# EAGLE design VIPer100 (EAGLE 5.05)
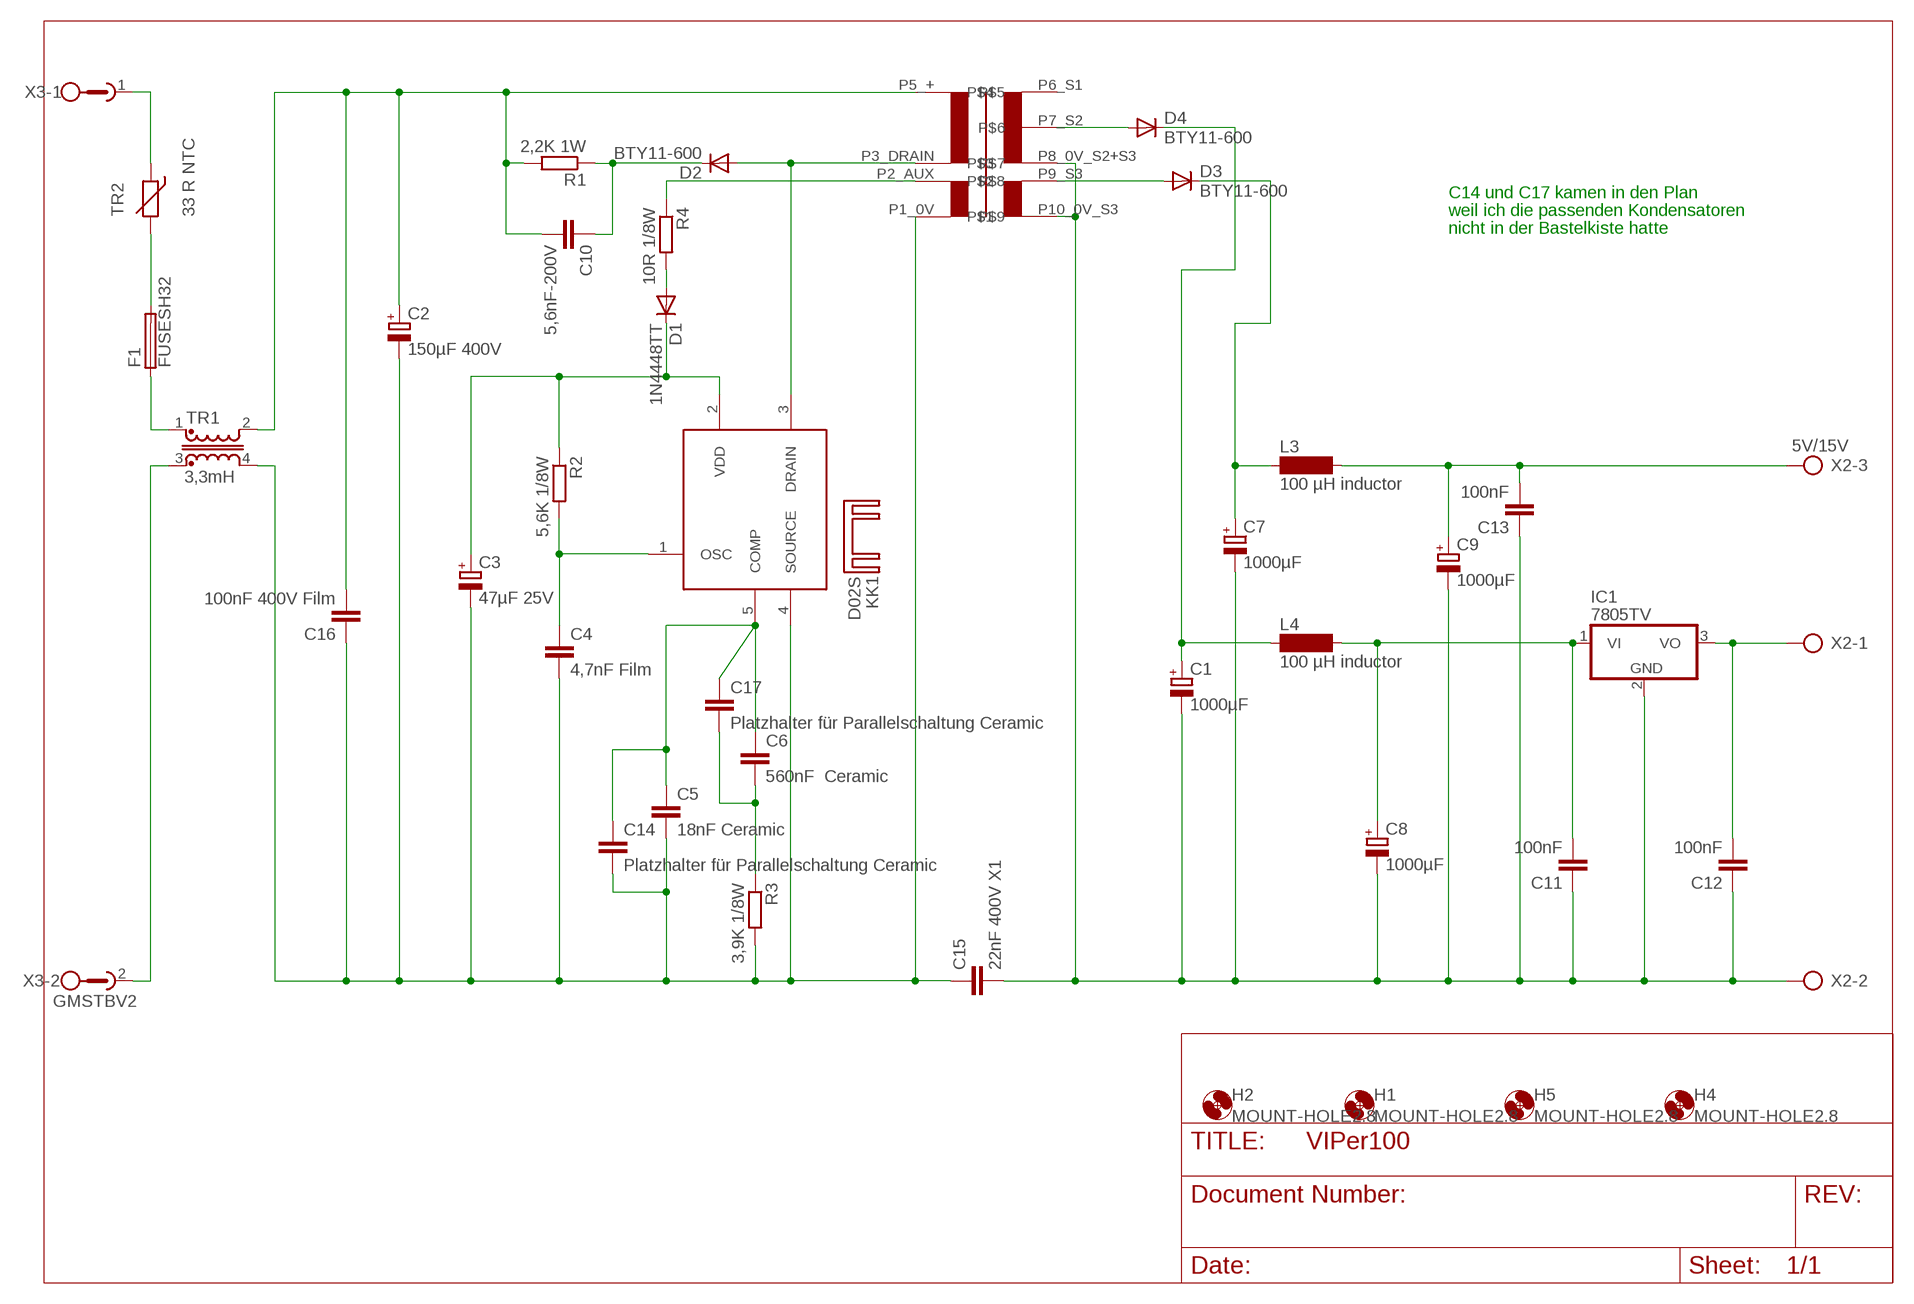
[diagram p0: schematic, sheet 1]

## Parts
C1  1000µF  CPOL-EUE5-8.5  [E5-8,5]
C2  150µF 400V  CPOL-EUE10-22.5  [EB22,5D]
C3  47µF 25V  CPOL-EUE5-5  [E5-5]
C4  4,7nF Film  C-EU050-025X075  [C050-025X075]
C5  18nF Ceramic  C-EU050-024X044  [C050-024X044]
C6  560nF Ceramic  C-EU050-024X044  [C050-024X044]
C7  1000µF  CPOL-EUE5-13  [E5-13]
C8  1000µF  CPOL-EUE5-8.5  [E5-8,5]
C9  1000µF  CPOL-EUE5-8.5  [E5-8,5]
C10  5,6nF-200V  C-EU225-074X268  [C225-074X268]
C11  100nF  C-EU025-025X050  [C025-025X050]
C12  100nF  C-EU025-025X050  [C025-025X050]
C13  100nF  C-EU025-025X050  [C025-025X050]
C14  Platzhalter für Parallelschaltung Ceramic  C-EU050-024X044  [C050-024X044]
C15  22nF 400V X1  C-EU102-064X133  [C102-064X133]
C16  100nF 400V Film  C-EU075-042X103  [C075-042X103]
C17  Platzhalter für Parallelschaltung Ceramic  C-EU050-024X044  [C050-024X044]
D1  1N4448TT  1N4148TT  [DO35-10]
D2  BTY11-600  1N4004GR  [C2992]
D3  BTY11-600  1N4004GR  [C2992]
D4  BTY11-600  1N4004GR  [C2992]
F1  FUSESH32  [SH32]
H1  MOUNT-HOLE2.8  [2,8]
H2  MOUNT-HOLE2.8  [2,8]
H4  MOUNT-HOLE2.8  [2,8]
H5  MOUNT-HOLE2.8  [2,8]
IC1  7805TV  [TO220V]
KK1  D02S  [D02S]
L3  100 µH inductor  SD12-1000  [SD12_1000]
L4  100 µH inductor  SD12-1000  [SD12_1000]
R1  2,2K 1W  R-EU0613/15  [P0613/15]
R2  5,6K 1/8W  R-EU0204/7L  [0207/7L]
R3  3,9K 1/8W  R-EU0207/7Q  [0207/7Q]
R4  10R 1/8W  R-EU0204/7L  [0207/7L]
TR1  3,3mH  U15-TRANSFORMER  [U15]
TR2  33 R NTC  THERMISTOR_R-7,5  [R-7,5]
U$2  MYRRA - 74030 - TRANSFORMATOR, EE25, 30W  HF_TRAFO_MYRRA  [EE25]
VIPER100A  VIPER100TO220HV  VIPER1002HINTEN  [T05D]
X2  5V/15V  AK300/3  [AK300/3]
X3  GMSTBV2  [GMSTBV2]

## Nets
GND1: C2.- C3.- C4.2 C5.2 C14.2 C15.1 C16.1 R3.P$2 TR1.4 U$2.P1_0V VIPER100A.4(SOURCE)
GND2: C1.- C7.- C8.- C9.- C11.1 C12.1 C13.1 C15.2 IC1.2(GND) U$2.P8_0V_S2+S3 U$2.P10_0V_S3 X2.2
N$1: C2.+ C10.2 C16.2 R1.2 TR1.2 U$2.P5_+
N$2: D2.A U$2.P3_DRAIN VIPER100A.3(DRAIN)
N$3: TR2.1 X3.1
N$4: F1.2A TR2.2
N$5: R4.P$1 U$2.P2_AUX
N$6: D1.A R4.P$2
N$7: C3.+ D1.C R2.P$1 VIPER100A.2(VDD)
N$8: C10.1 D2.C R1.1
N$9: C5.1 C6.1 C14.1 C17.1 VIPER100A.5(COMP)
N$10: C6.2 C17.2 R3.P$1
N$11: C4.1 R2.P$2 VIPER100A.1(OSC)
N$12: TR1.3 X3.2
N$13: F1.1A TR1.1
N$14: D4.A U$2.P7_S2
N$15: C8.+ C11.2 IC1.1(VI) L4.2
N$16: D3.A U$2.P9_S3
N$18: C1.+ D4.C L4.1
N$19: C7.+ D3.C L3.1
N$20: C9.+ C13.2 L3.2 X2.3
N$22: C12.2 IC1.3(VO) X2.1
Unconnected: U$2.P6_S1

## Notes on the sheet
- C14 und C17 kamen in den Plan
- weil ich die passenden Kondensatoren
- nicht in der Bastelkiste hatte

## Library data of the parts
C1-C3 C7-C9 = rcl:CPOL-EU: POLARIZED CAPACITOR, European symbol
C4-C6 C10-C17 = rcl:C-EU: CAPACITOR, European symbol
D1 = Axel2:1N4148: DIODE
D2-D4 = Axel2:1N4004: DIODE
F1 = fuse:FUSE: Fuse
H1 H2 H4 H5 = holes:MOUNT-HOLE: MOUNTING HOLE with drill center marker
IC1 = linear:78*: Positive VOLTAGE REGULATOR Source: http://cache.national.com/ds/LM/LM78L05.pdf http://www.fairchildsemi.com/ds/LM/LM7805.pdf
KK1 = heatsink:D02S: HEATSINK
L3 L4 = inductor-neosid:SD12: INDUCTOR
R1-R4 = Axel2:R-EU: RESISTOR, European symbol
TR1 = inductor-neosid:U15: TRANSFORMER U15
TR2 = discrete:THERMISTOR_: Thermo Resistor
U$2 = Axel2:HF_TRAFO_MYRRA
VIPER100A = Axel2:VIPER100
X2 = Axel2:AK300/3: CONNECTOR
X3 = con-phoenix-508:GMSTBV2: PHOENIX

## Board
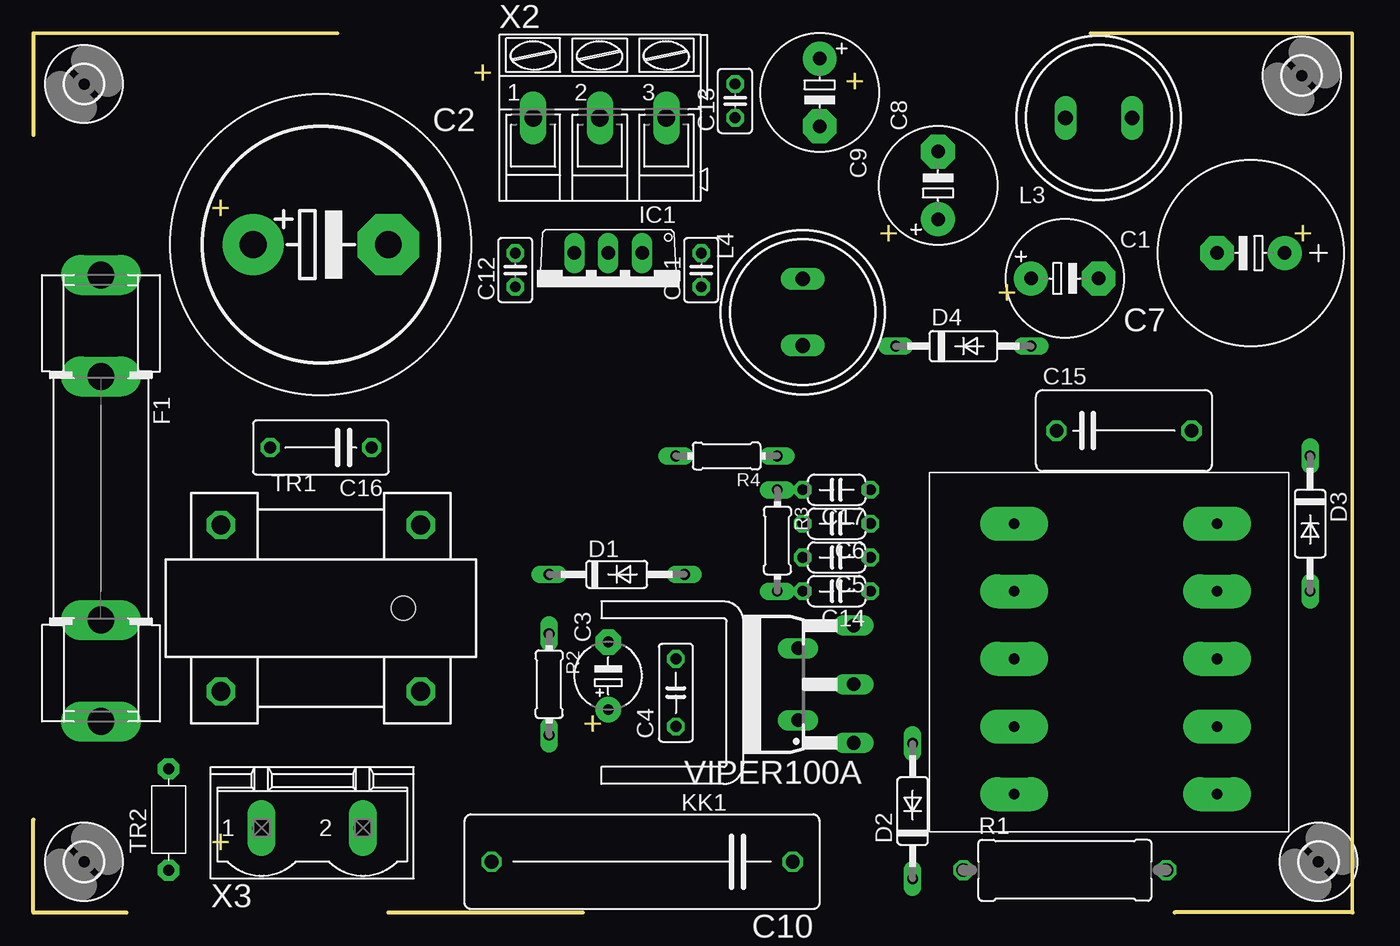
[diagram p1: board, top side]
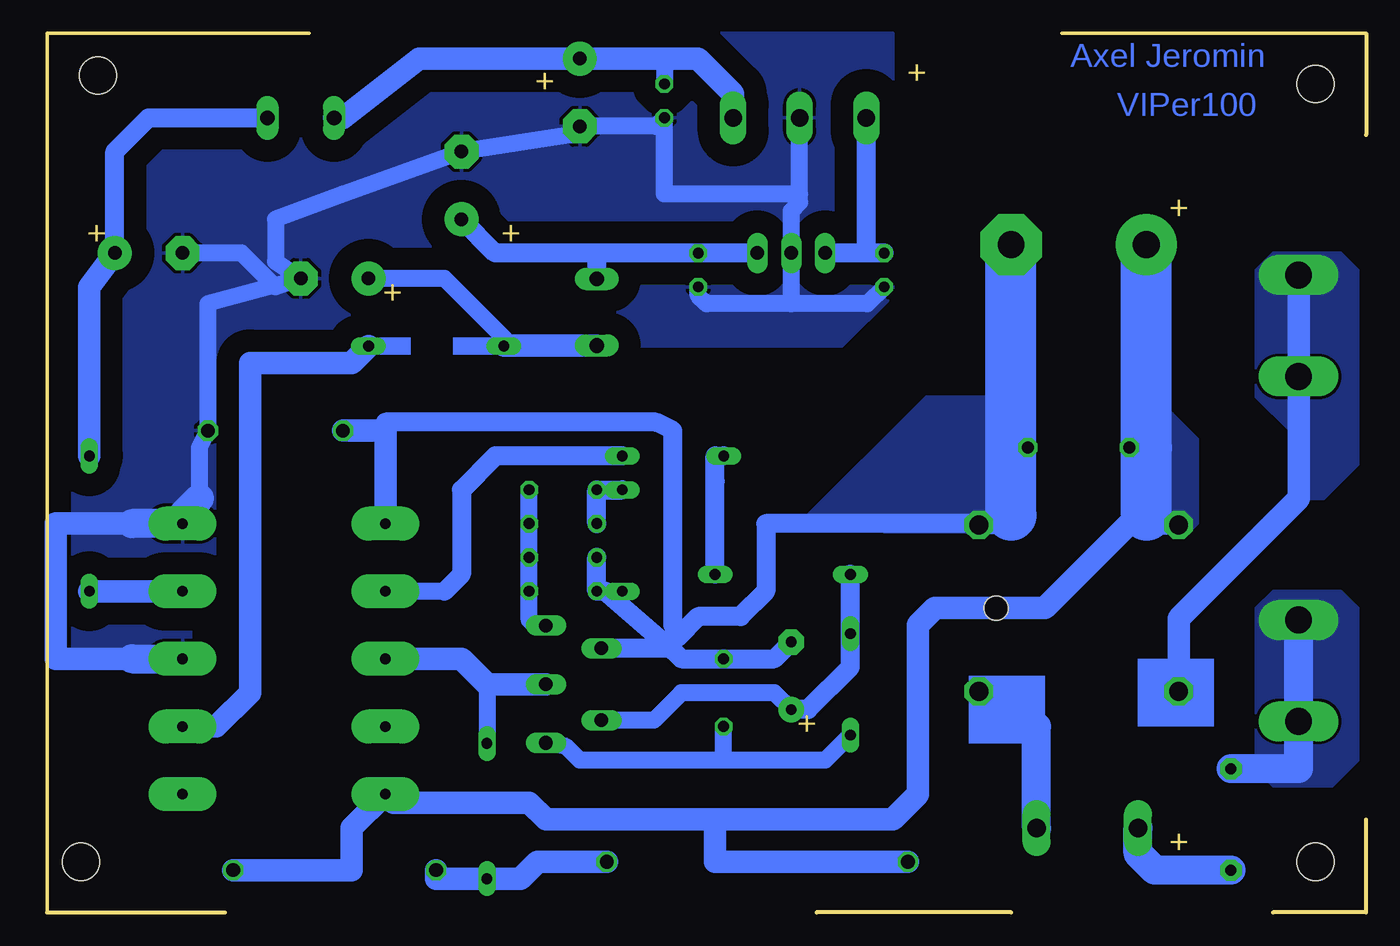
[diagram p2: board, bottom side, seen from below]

Size 99.06 x 66.04 mm. Coordinates in mm from the lower left corner, seen from the top.
Outline: 0,58.42 0,66.04 22.86,66.04
Outline: 0,6.99 0,0 6.99,0
Outline: 85.72,0 99.06,0 99.06,66.04 79.38,66.04
Outline: 26.67,0 41.27,0
Copper layers (1*16): Top 0.035mm / dielectric 1.5mm / Bottom 0.035mm
Design rules "default *": minimum track width 10mil, minimum drill 24mil, track to track 8mil, track to pad 8mil, pad to pad 8mil, via to via 8mil, smd to smd 8mil, copper to edge 40mil, drill to drill 8mil, minimum pad ring 10mil, minimum via ring 8mil, stop-mask expansion 4mil, vias tented up to drill 0mil, thermal gap 10mil

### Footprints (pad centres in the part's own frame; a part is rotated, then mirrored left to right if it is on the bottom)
E5-8,5 = drill 1.016 pad 2.54 round: + -2.54,0 | drill 1.016 pad 2.54 octagon: - 2.54,0
EB22,5D = drill 2.007 pad 4.597 round: + -5.08,0 | drill 2.007 pad 4.597 octagon: - 5.08,0
E5-5 = drill 0.813 pad 1.905 round: + -2.54,0 | drill 0.813 pad 1.905 octagon: - 2.54,0
C050-025X075 = drill 0.813 octagon: 1 -2.54,0; 2 2.54,0
C050-024X044 = drill 0.813 octagon: 1 -2.54,0; 2 2.54,0
E5-13 = drill 1.016 pad 2.54 round: + -2.54,0 | drill 1.016 pad 2.54 octagon: - 2.54,0
C225-074X268 = drill 1.016 octagon: 1 -11.303,0; 2 11.303,0
C025-025X050 = drill 0.813 octagon: 1 -1.27,0; 2 1.27,0
C102-064X133 = drill 1.016 octagon: 1 -5.08,0; 2 5.08,0
C075-042X103 = drill 0.914 octagon: 1 -3.81,0; 2 3.81,0
DO35-10 = drill 0.813 long: A 5.08,0; C -5.08,0
C2992 = drill 0.813 long: A 5.08,0; C -5.08,0
SH32 = drill 2.007 long: 1A -16.764,0; 1B -9.144,0; 2A 9.144,0; 2B 16.764,0
2,8 = hole 2.8: 0,0
TO220V = drill 1.016 long: 1 -2.54,-2.54; 2 0,-2.54; 3 2.54,-2.54
SD12_1000 = drill 1.1 long: 1 -2.5,0; 2 2.5,0
P0613/15 = drill 1.016 octagon: 1 -7.62,0; 2 7.62,0
0207/7L = drill 0.8 long: P$1 -3.81,0; P$2 3.81,0
0207/7Q = drill 0.8 long: P$1 -3.81,0; P$2 3.81,0
U15 = drill 1.422 octagon: 1 -7.5,-6.25; 2 -7.5,6.25; 3 7.5,-6.25; 4 7.5,6.25 | hole 1.8: 6.2,0
R-7,5 = drill 0.813 pad 1.6 octagon: 1 -3.81,0; 2 3.81,0
EE25 = drill 0.8 pad 2.54 long: P1_0V -7.62,10.16; P2_AUX -7.62,5.08; P3_DRAIN -7.62,0; P4_FREI -7.62,-5.08; P5_+ -7.62,-10.16; P6_S1 7.62,-10.16; P7_S2 7.62,-5.08; P8_0V_S2+S3 7.62,0; P9_S3 7.62,5.08; P10_0V_S3 7.62,10.16
T05D = drill 1.016 long: 1 -4.404,-5.08; 2 -2.702,-0.914; 3 0,-5.08; 4 2.702,-0.914; 5 4.404,-5.08
AK300/3 = drill 1.321 long: 1 -5.004,0; 2 0,0; 3 5.004,0
GMSTBV2 = drill 1.397 long: 1 -3.81,0; 2 3.81,0

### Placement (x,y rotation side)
C1  77.47,47.62 0 top
C2  21.59,50.16 0 top
C3  43.18,17.78 90 top
C4  48.26,16.51 90 top
C5  60.33,26.67 180 top
C6  60.33,29.21 180 top
C7  91.44,49.53 180 top
C8  67.94,54.61 90 top
C9  59.05,61.59 270 top
C10  45.72,3.81 180 top
C11  50.16,48.26 90 top
C12  36.2,48.26 90 top
C13  52.7,60.96 90 top
C14  60.33,24.13 180 top
C15  81.92,36.2 0 top
C16  21.59,34.92 180 top
C17  60.33,31.75 180 top
D1  43.81,25.4 0 top
D2  66.04,7.62 90 top
D3  95.89,29.21 270 top
D4  69.85,42.55 0 top
F1  5.08,31.11 270 top
H1  3.81,62.23 0 top
H2  95.25,62.87 0 top
H4  3.81,3.81 0 top
H5  96.52,3.81 0 top
IC1  43.18,46.99 180 top
KK1  52.07,16.51 90 top
L3  80.01,59.69 180 top
L4  57.78,45.09 90 top
R1  77.47,3.17 0 top
R2  38.73,17.14 270 top
R3  55.88,27.94 270 top
R4  52.07,34.29 180 top
TR1  21.59,22.86 0 top
TR2  10.16,6.99 90 top
U$2  81.28,19.05 0 top
VIPER100A  56.52,17.14 90 top
X2  42.55,59.69 0 top
X3  20.95,6.35 0 top

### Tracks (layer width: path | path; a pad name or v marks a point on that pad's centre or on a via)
GND1
  Bottom 1.27: 73.66,36.83 73.66,36.2 | C16.1 26.67,34.92 27.94,34.92 | C14.2 R3.P$2 C14.2
  Bottom 1.422: C5.2 C14.2 57.15,24.13 52.07,19.68 | C3.- 44.45,19.05 C4.2 51.44,19.05 52.07,19.68 | VIPER100A.4 52.54,19.85 52.39,20 | 51.75,20.64 50.16,22.23 46.99,22.23 45.09,24.13 45.09,29.21 29.19,29.21 TR1.4 27.41,29.11 26.67,29.84 | 51.75,20.64 52.39,20 | 52.39,20 52.07,19.68 | 73.66,36.83 53.34,36.83 52.07,36.2 52.07,21.59 51.75,20.64
  Bottom 1.676: C15.1 73.66,36.2 U$2.P1_0V
  Bottom 3.81: 26.67,29.84 26.67,34.92 C2.-
  pour Bottom: 26.04,41.91 26.67,41.91 26.67,28.57
  pour Bottom (no thermals): 36.2,28.57 27.94,28.57 26.04,30.48 26.04,38.73 33.02,38.73 42.55,29.21 36.83,29.21
GND2
  Bottom 1.27: 42.55,53.98 42.55,53.34 43.18,52.7 IC1.2 43.18,45.72 | 42.55,53.98 X2.2 | 87.63,31.11 87.63,34.92 C15.2 87,45.72 C1.- | 88.9,29.84 U$2.P10_0V_S3 | C11.1 50.16,46.35 49.53,45.72 43.18,45.72 | C12.1 37.47,45.72 43.18,45.72 | C7.- 84.45,49.53 81.92,46.99 C1.- | 42.55,53.98 52.7,53.98 C13.1 53.34,59.05 C9.- 59.69,58.42 C8.- 76.83,53.98 81.92,52.07 81.92,48.9 C1.-
  Bottom 1.676: 92.71,19.05 98.42,19.05 98.42,29.21 92.71,29.21
  Bottom 2.184: 92.71,19.05 U$2.P8_0V_S2+S3 | U$2.P10_0V_S3 92.71,29.21 | 87.63,31.11 88.9,29.84
  pour Bottom (isolate 1.676): 35.56,66.04 35.56,46.35 39.37,42.55 83.19,42.55 84.45,25.4 88.27,21.59 88.27,18.41 99.06,18.41 99.06,66.04
N$1
  Bottom 1.27: 16.51,29.84 15.88,30.48 14.61,29.21 | 16.51,34.92 C16.2
  Bottom 1.676: R1.2 76.2,3.17 76.2,6.35 U$2.P5_+ 73.03,8.26 62.87,8.26 61.59,6.99 48.9,6.99 | C10.2 48.9,3.81 48.9,6.99 | 48.9,6.99 35.56,6.99 33.66,8.89 33.66,21.59 32.38,22.86 24.13,22.86 17.78,29.21 14.61,29.21 14.19,29.21 TR1.2
  Bottom 3.81: 16.51,29.84 16.51,34.92 C2.+
  pour Bottom (no thermals): 16.51,28.57 13.34,28.57 12.7,29.21 12.7,35.56 15.24,38.1 17.14,36.2 17.14,29.21
N$2
  Bottom 1.27: 66.04,17.14 D2.A
  Bottom 1.676: VIPER100A.3 66.04,17.14 67.94,19.05 U$2.P3_DRAIN
N$3
  Bottom 2.184: X3.1 17.14,4.45 15.88,3.17 TR2.1
N$4
  Bottom 2.184: TR2.2 5.08,10.79 F1.2A
  pour Bottom (no thermals): 6.99,9.53 2.54,9.53 0.64,11.43 0.64,22.86 1.27,23.5 1.91,24.13 6.99,24.13 8.26,22.86 8.26,10.79
N$5
  Bottom 1.27: 69.22,24.13 U$2.P2_AUX
  Bottom 1.422: R4.P$1 65.41,34.29 67.94,31.75 67.94,25.4 69.22,24.13
N$6
  Bottom 1.422: D1.A 48.9,32.38 48.9,34.29 R4.P$2
N$7
  Bottom 1.27: C3.+ 44.45,16.51 51.44,16.51 53.5,14.44 VIPER100A.2
  Bottom 1.422: D1.C R2.P$1 38.73,18.41 41.91,15.24 C3.+
N$8
  Bottom 1.676: C10.1 62.23,3.81 63.5,2.54 D2.C 69.85,2.54 R1.1
N$9
  Bottom 1.27: C17.1 C6.1 C5.1 C14.1 62.87,21.96 62.45,21.55 VIPER100A.5
N$10
  Bottom 1.422: C6.2 C17.2 R3.P$1
N$11
  Bottom 1.27: VIPER100A.1 60.1,12.47 59.05,11.43 48.26,11.43 | 48.26,11.43 C4.1 | 48.26,11.43 40.64,11.43 R2.P$2
N$12
  Bottom 1.676: TR1.3 27.41,16.61 24.77,13.97
  Bottom 2.184: X3.2 24.77,13.97
N$13
  Bottom 1.676: TR1.1 14.09,22.11 5.08,31.11 F1.1A
  pour Bottom (no thermals): 5.08,31.11 3.17,31.11 1.27,33.02 0.64,33.66 0.64,48.26 1.91,49.53 6.99,49.53 8.26,48.26 8.26,38.73 5.71,36.2 5.71,31.75
N$14
  Bottom 1.676: U$2.P7_S2 86.36,13.97 83.82,16.51 83.82,41.27 76.2,41.27 D4.A
N$15
  Bottom 1.422: IC1.1 C11.2 57.78,49.53 | 57.78,49.53 65.41,49.53 C8.+ | 57.78,49.53 L4.2
N$16
  Bottom 1.676: U$2.P9_S3 D3.A
N$18
  Bottom 1.27: 64.73,42.59 D4.C 64.77,43.18 69.22,47.62 C1.+
  Bottom 1.676: L4.1 64.73,42.59
N$19
  Bottom 1.422: L3.1 91.44,59.69 93.98,57.15 C7.+
  Bottom 1.676: D3.C 95.89,46.99 C7.+
N$20
  Bottom 1.27: 52.7,64.14 C13.2
  Bottom 1.676: X2.3 47.55,61.52 50.16,64.14 52.7,64.14 C9.+ 71.12,64.14 76.88,59.65 L3.2
N$22
  Bottom 1.422: C12.2 37.47,49.53 | 37.47,49.53 IC1.3 | X2.1 37.54,49.61 37.47,49.53
(copper drawn outside any net)
  shapes: Bottom area x4

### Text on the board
Bottom: Axel Jeromin | VIPer100
Dimension: + | + | + | + | + | + | + | +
